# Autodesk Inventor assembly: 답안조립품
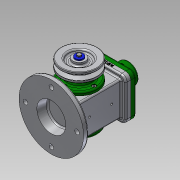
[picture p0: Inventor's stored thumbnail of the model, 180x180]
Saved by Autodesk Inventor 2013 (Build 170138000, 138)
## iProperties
Created: 2018-10
Part Number: 답안조립품
Document SubType Name: Assembly
Designer: hana-cad17
Author: hana-cad17
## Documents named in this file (18)
- C:\Documents and Settings\hana-cad17\바탕 화면\481007V1042\답안조립품.iam
- C:\Documents and Settings\hana-cad17\바탕 화면\481007V1042\본체.ipt
- C:\Documents and Settings\hana-cad17\바탕 화면\481007V1042\앞커버.ipt
- C:\Documents and Settings\hana-cad17\바탕 화면\481007V1042\뒤커버.ipt
- C:\Documents and Settings\hana-cad17\바탕 화면\481007V1042\오일 실 17 30 8.ipt
- C:\Documents and Settings\hana-cad17\바탕 화면\481007V1042\볼트 M4 x 8.ipt
- C:\Documents and Settings\hana-cad17\바탕 화면\481007V1042\편심축.ipt
- C:\Documents and Settings\hana-cad17\바탕 화면\481007V1042\베어링 17 x 40 x 12.ipt
- C:\Documents and Settings\hana-cad17\바탕 화면\481007V1042\링크.ipt
- C:\Documents and Settings\hana-cad17\바탕 화면\481007V1042\슬라이더.ipt
- C:\Documents and Settings\hana-cad17\바탕 화면\481007V1042\클레비스 핀 6 x 22.ipt
- 클레비스 핀 6 x 22.ipt
- C:\Documents and Settings\hana-cad17\바탕 화면\481007V1042\E-링.ipt
- C:\Documents and Settings\hana-cad17\바탕 화면\481007V1042\덮개.ipt
- C:\Documents and Settings\hana-cad17\바탕 화면\481007V1042\키 4 x 4 x 12.ipt
- C:\Documents and Settings\hana-cad17\바탕 화면\481007V1042\V-벨트풀리.ipt
- C:\Documents and Settings\hana-cad17\바탕 화면\481007V1042\와셔 4x16.ipt
- C:\Documents and Settings\hana-cad17\바탕 화면\481007V1042\볼트 M4 x 10.ipt
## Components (2 placed, 2 different names)
1. E-링:1
2. V-벨트풀리:1
